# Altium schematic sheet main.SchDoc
size A; SheetNumber: 1
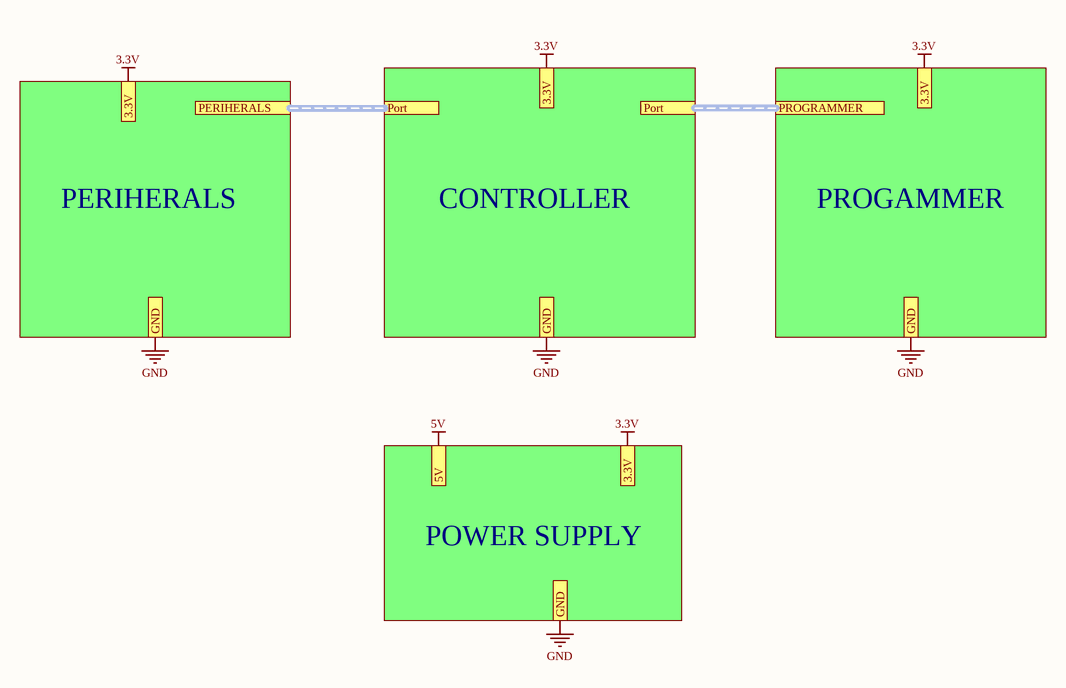
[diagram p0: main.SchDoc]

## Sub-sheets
CONTROLLER = controller.SchDoc: no entries
PERIHERALS = INPUT AND OUPUT.SchDoc: no entries
POWER SUPPLY = PowerSupply.SchDoc: no entries
PROGAMMER = Programmer.SchDoc: no entries

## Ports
3.3V, 5V, GND, PERIHERALS (harness PERIHERALS), Port, PROGRAMMER (harness PROGRAMMER)

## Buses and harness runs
harness port PERIHERALS = port Port
harness port Port = port PROGRAMMER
